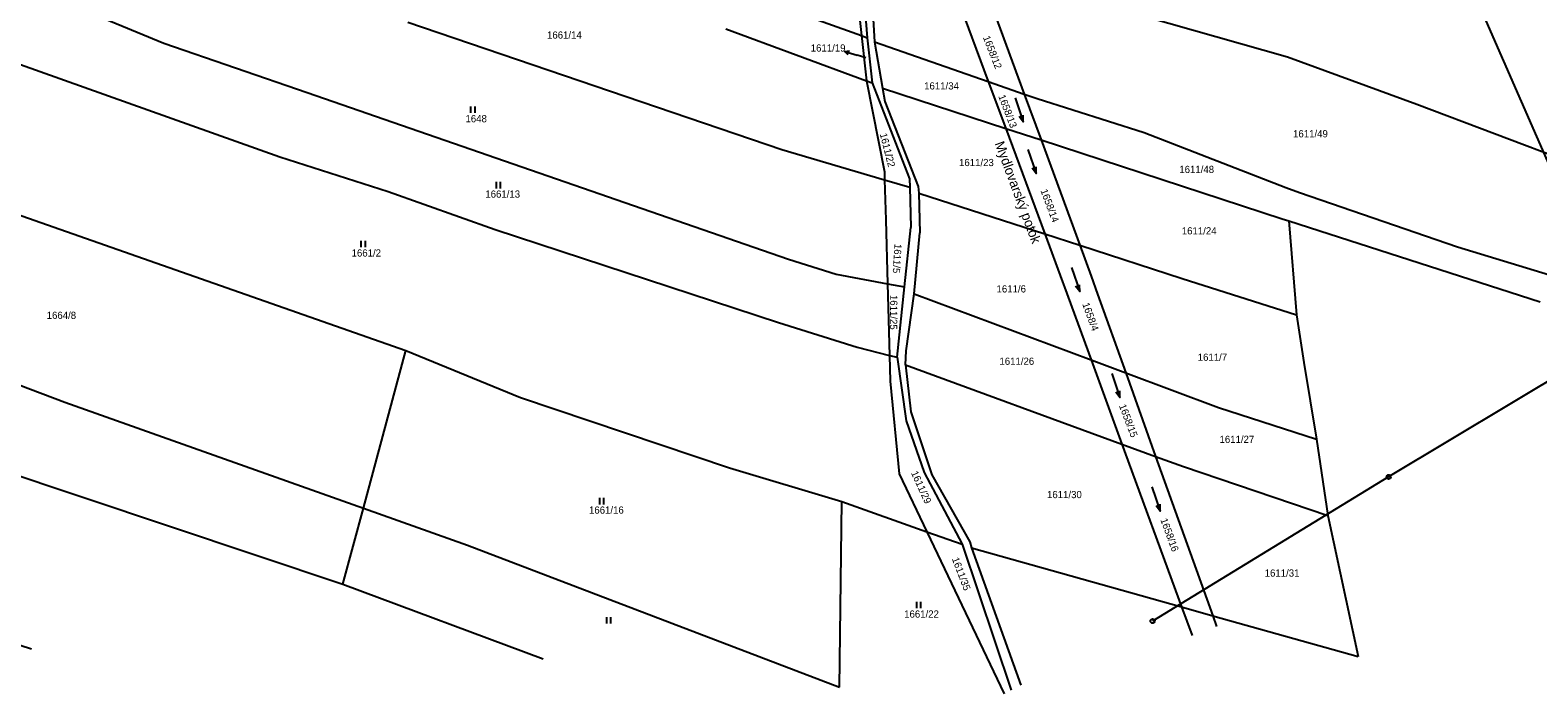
# Model space of a CAD drawing. Extents: x -763205 to -760228, y -1155311 to -1152844.
# Drawn here: x -761366.2 to -761010, y -1155167.3 to -1155010.6 of the extents above; entities that cross this region are included whole.
import ezdxf

# ---------------------------------------------------------------- set-up
doc = ezdxf.new("R2010")
doc.units = 0
for name, color, linetype in [('Vrstva 1', 7, 'Continuous'), ('Vrstva 12', 7, 'Continuous'), ('Vrstva 15', 7, 'Continuous'), ('Vrstva 16', 7, 'Continuous'), ('Vrstva 18', 7, 'Continuous'), ('Vrstva 25', 7, 'Continuous'), ('Vrstva 26', 7, 'Continuous'), ('Vrstva 6', 7, 'Continuous')]:
    doc.layers.add(name, color=color, linetype=linetype)

msp = doc.modelspace()

# ---------------------------------------------------------------- linework, layer by layer
at = {"layer": 'Vrstva 1'}
for p, q in [((-761172.54, -1154986.65), (-761169.79, -1155011.88)), ((-761151.21, -1154991.93), (-761139.81, -1155022.71)), ((-761142.75, -1154994.66), (-761131.35, -1155025.67)), ((-761169.79, -1155011.88), (-761168.71, -1155021.84)), ((-761168.71, -1155021.84), (-761168.58, -1155022.51)), ((-761168.58, -1155022.51), (-761164.37, -1155044.02)), ((-761139.81, -1155022.71), (-761135.71, -1155033.79)), ((-761131.35, -1155025.67), (-761127.36, -1155036.51)), ((-761135.71, -1155033.79), (-761126.49, -1155058.69)), ((-761417.92, -1155036.97), (-761277.43, -1155086.2)), ((-761127.36, -1155036.51), (-761118.22, -1155061.38)), ((-761164.37, -1155044.02), (-761164.32, -1155045.89)), ((-761164.32, -1155045.89), (-761164.05, -1155055.4)), ((-761164.05, -1155055.4), (-761163.62, -1155070.47)), ((-761126.49, -1155058.69), (-761122.29, -1155070.04)), ((-761118.22, -1155061.38), (-761115.54, -1155068.66)), ((-761163.62, -1155070.47), (-761163.14, -1155087.37)), ((-761122.29, -1155070.04), (-761121.84, -1155071.26)), ((-761121.84, -1155071.26), (-761115.54, -1155088.43)), ((-761115.54, -1155068.66), (-761114.02, -1155072.89)), ((-761114.02, -1155072.89), (-761107.35, -1155091.49)), ((-761287.49, -1155123.44), (-761277.43, -1155086.2)), ((-761163.14, -1155087.37), (-761162.97, -1155093.45)), ((-761115.54, -1155088.43), (-761108.25, -1155108.3)), ((-761107.35, -1155091.49), (-761100.28, -1155111.21)), ((-761162.97, -1155093.45), (-761160.85, -1155115.32)), ((-761108.25, -1155108.3), (-761094.13, -1155146.77)), ((-761376.78, -1155113.13), (-761292.34, -1155141.39)), ((-761100.28, -1155111.21), (-761086.78, -1155148.83)), ((-761160.85, -1155115.32), (-761154.31, -1155129.02)), ((-761292.34, -1155141.39), (-761287.49, -1155123.44)), ((-761154.31, -1155129.02), (-761136.03, -1155167.28)), ((-761094.13, -1155146.77), (-761091.64, -1155153.54)), ((-761086.78, -1155148.83), (-761085.86, -1155151.41))]:
    msp.add_line(p, q, dxfattribs=at)
at = {"layer": 'Vrstva 12'}
for p, q in [((-760989.63, -1155082.73), (-761022.16, -1155008.41)), ((-760989.63, -1155082.73), (-761045.22, -1155116.06)), ((-761045.22, -1155116.06), (-761100.99, -1155150.1))]:
    msp.add_line(p, q, dxfattribs=at)
at = {"layer": 'Vrstva 16'}
for p in [(-761173.7, -1155015.645), (-761168.75, -1155017.15)]:
    msp.add_line(p, (-761170.83, -1155016.52), dxfattribs=at)
msp.add_lwpolyline([(-761172.889, -1155016.415), (-761173.7, -1155015.645), (-761172.597, -1155015.459)], dxfattribs=at)
at = {"layer": 'Vrstva 25'}
for p, q in [((-761262.1, -1155030.13), (-761262.1, -1155028.63)), ((-761261.1, -1155030.13), (-761261.1, -1155028.63)), ((-761256.06, -1155047.93), (-761256.06, -1155046.43)), ((-761255.06, -1155047.93), (-761255.06, -1155046.43)), ((-761287.97, -1155061.84), (-761287.97, -1155060.34)), ((-761286.97, -1155061.84), (-761286.97, -1155060.34)), ((-761231.64, -1155122.54), (-761231.64, -1155121.04)), ((-761230.64, -1155122.54), (-761230.64, -1155121.04)), ((-761156.73, -1155147.09), (-761156.73, -1155145.59)), ((-761155.73, -1155147.09), (-761155.73, -1155145.59)), ((-761229.97, -1155150.71), (-761229.97, -1155149.21)), ((-761228.97, -1155150.71), (-761228.97, -1155149.21))]:
    msp.add_line(p, q, dxfattribs=at)
for points in [[(-761133.501, -1155026.551), (-761131.559, -1155032.229), (-761131.571, -1155030.647)], [(-761131.559, -1155032.229), (-761132.518, -1155030.971)], [(-761130.471, -1155038.781), (-761128.529, -1155044.459), (-761128.541, -1155042.877)], [(-761128.529, -1155044.459), (-761129.488, -1155043.201)], [(-761120.161, -1155066.581), (-761118.219, -1155072.259), (-761118.231, -1155070.677)], [(-761118.219, -1155072.259), (-761119.178, -1155071.001)], [(-761110.661, -1155091.651), (-761108.719, -1155097.329), (-761108.731, -1155095.747)], [(-761108.719, -1155097.329), (-761109.678, -1155096.071)], [(-761101.161, -1155118.441), (-761099.219, -1155124.119), (-761099.231, -1155122.537)], [(-761099.219, -1155124.119), (-761100.178, -1155122.861)]]:
    msp.add_lwpolyline(points, dxfattribs=at)
at = {"layer": 'Vrstva 26'}
for centre in [(-761045.22, -1155116.06), (-761100.99, -1155150.1)]:
    msp.add_circle(centre, 0.5, dxfattribs=at)
at = {"layer": 'Vrstva 6'}
for p, q in [((-761277.5, -1154973.14), (-761169.79, -1155011.88)), ((-761168.17, -1154988.95), (-761166.71, -1155013.3)), ((-761170.15, -1154990.02), (-761168.47, -1155012.36)), ((-761357.13, -1155004.33), (-761334.64, -1155013.67)), ((-761108.27, -1155005.79), (-761069.13, -1155016.91)), ((-761276.94, -1155008.72), (-761188.63, -1155038.79)), ((-761201.82, -1155010.26), (-761168.58, -1155022.51)), ((-761380.91, -1155014.27), (-761307.23, -1155040.5)), ((-761334.64, -1155013.67), (-761300.75, -1155025.32)), ((-761169.79, -1155011.88), (-761168.47, -1155012.36)), ((-761168.47, -1155012.36), (-761167.28, -1155022.99)), ((-761166.71, -1155013.3), (-761139.81, -1155022.71)), ((-761166.71, -1155013.3), (-761164.8, -1155024.29)), ((-761069.13, -1155016.91), (-761038.56, -1155028.06)), ((-761168.58, -1155022.51), (-761167.28, -1155022.99)), ((-761167.28, -1155022.99), (-761158.44, -1155045.68)), ((-761164.8, -1155024.29), (-761164.28, -1155027.45)), ((-761164.8, -1155024.29), (-761135.71, -1155033.79)), ((-761139.81, -1155022.71), (-761131.35, -1155025.67)), ((-761300.75, -1155025.32), (-761187.02, -1155064.68)), ((-761164.28, -1155027.45), (-761156.4, -1155047.53)), ((-761131.35, -1155025.67), (-761128.27, -1155026.75)), ((-761128.27, -1155026.75), (-761103.01, -1155034.72)), ((-761038.56, -1155028.06), (-760999.22, -1155042.88)), ((-761135.71, -1155033.79), (-761127.36, -1155036.51)), ((-761103.01, -1155034.72), (-761069.47, -1155047.71)), ((-761188.63, -1155038.79), (-761164.32, -1155045.89)), ((-761127.36, -1155036.51), (-761070.41, -1155055.1)), ((-761307.23, -1155040.5), (-761281.64, -1155048.64)), ((-761164.32, -1155045.89), (-761158.36, -1155047.63)), ((-761158.44, -1155045.68), (-761158.36, -1155047.63)), ((-761281.64, -1155048.64), (-761256.35, -1155057.67)), ((-761158.36, -1155047.63), (-761158.14, -1155057.21)), ((-761156.4, -1155047.53), (-761156.25, -1155049.03)), ((-761156.25, -1155049.03), (-761155.97, -1155058.42)), ((-761156.25, -1155049.03), (-761126.49, -1155058.69)), ((-761069.47, -1155047.71), (-761066.27, -1155048.93)), ((-761066.27, -1155048.93), (-761028.93, -1155061.73)), ((-761070.41, -1155055.1), (-761068.82, -1155055.61)), ((-761068.82, -1155055.61), (-761067, -1155077.76)), ((-761068.82, -1155055.61), (-761009.39, -1155074.74)), ((-761458.43, -1155060.54), (-761358.05, -1155098.4)), ((-761256.35, -1155057.67), (-761189.42, -1155079.64)), ((-761159.64, -1155071.21), (-761158.14, -1155057.21)), ((-761157.36, -1155072.81), (-761155.97, -1155058.42)), ((-761126.49, -1155058.69), (-761118.22, -1155061.38)), ((-761118.22, -1155061.38), (-761094.02, -1155069.24)), ((-761028.93, -1155061.73), (-761007.24, -1155068.34)), ((-761187.02, -1155064.68), (-761175.74, -1155068.21)), ((-761175.74, -1155068.21), (-761163.62, -1155070.47)), ((-761163.62, -1155070.47), (-761159.64, -1155071.21)), ((-761161.35, -1155087.82), (-761159.64, -1155071.21)), ((-761094.02, -1155069.24), (-761067, -1155077.76)), ((-761159.24, -1155086.32), (-761157.36, -1155072.81)), ((-761157.36, -1155072.81), (-761115.54, -1155088.43)), ((-761067, -1155077.76), (-761065.29, -1155089.06)), ((-761189.42, -1155079.64), (-761170.8, -1155085.43)), ((-761170.8, -1155085.43), (-761163.14, -1155087.37)), ((-761277.43, -1155086.2), (-761250.37, -1155097.33)), ((-761163.14, -1155087.37), (-761161.35, -1155087.82)), ((-761161.35, -1155087.82), (-761159.25, -1155102.83)), ((-761159.35, -1155089.62), (-761159.24, -1155086.32)), ((-761115.54, -1155088.43), (-761107.35, -1155091.49)), ((-761065.29, -1155089.06), (-761062.29, -1155107.15)), ((-761159.35, -1155089.62), (-761158.13, -1155100.7)), ((-761159.35, -1155089.62), (-761108.25, -1155108.3)), ((-761107.35, -1155091.49), (-761085.4, -1155099.69)), ((-761358.05, -1155098.4), (-761287.49, -1155123.44)), ((-761250.37, -1155097.33), (-761200.99, -1155113.9)), ((-761085.4, -1155099.69), (-761062.29, -1155107.15)), ((-761159.25, -1155102.83), (-761154.99, -1155115.02)), ((-761158.13, -1155100.7), (-761153.12, -1155115.6)), ((-761108.25, -1155108.3), (-761100.28, -1155111.21)), ((-761062.29, -1155107.15), (-761059.59, -1155125.14)), ((-761200.99, -1155113.9), (-761174.45, -1155121.89)), ((-761100.28, -1155111.21), (-761093.71, -1155113.61)), ((-761093.71, -1155113.61), (-761059.59, -1155125.14)), ((-761154.99, -1155115.02), (-761146, -1155131.96)), ((-761153.12, -1155115.6), (-761144.21, -1155131.39)), ((-761287.49, -1155123.44), (-761262.87, -1155132.18)), ((-761174.94, -1155165.67), (-761174.45, -1155121.89)), ((-761174.45, -1155121.89), (-761154.31, -1155129.02)), ((-761059.59, -1155125.14), (-761052.4, -1155158.5)), ((-761154.31, -1155129.02), (-761146, -1155131.96)), ((-761144.21, -1155131.39), (-761143.76, -1155132.82)), ((-761262.87, -1155132.18), (-761174.94, -1155165.67)), ((-761146, -1155131.96), (-761134.38, -1155166.4)), ((-761143.76, -1155132.82), (-761132.16, -1155165.22)), ((-761143.76, -1155132.82), (-761094.13, -1155146.77)), ((-761292.34, -1155141.39), (-761245.01, -1155159)), ((-761390.25, -1155148.78), (-761365.93, -1155156.67)), ((-761094.13, -1155146.77), (-761086.78, -1155148.83)), ((-761086.78, -1155148.83), (-761052.4, -1155158.5))]:
    msp.add_line(p, q, dxfattribs=at)

# ---------------------------------------------------------------- texts
at = {"layer": 'Vrstva 15'}
msp.add_text('Mydlovarský potok', height=2.3, rotation=290.43231, dxfattribs=at).set_placement((-761138.331, -1155037.333))
at = {"layer": 'Vrstva 16'}
msp.add_text('1611/19', height=1.7, dxfattribs=at).set_placement((-761181.777, -1155015.64))
at = {"layer": 'Vrstva 18'}
for s, height, p in [('1661/14', 1.7, (-761244.087, -1155012.58)), ('1611/19', 0.1, (-761168.727, -1155017.15)), ('1611/34', 1.7, (-761154.977, -1155024.59)), ('1648', 1.7, (-761263.357, -1155032.33)), ('1611/49', 1.7, (-761067.797, -1155035.89)), ('1611/23', 1.7, (-761146.727, -1155042.68)), ('1611/48', 1.7, (-761094.677, -1155044.31)), ('1661/13', 1.7, (-761258.667, -1155050.13)), ('1611/24', 1.7, (-761094.087, -1155058.81)), ('1661/2', 1.7, (-761290.267, -1155064.04)), ('1611/6', 1.7, (-761137.867, -1155072.52)), ('1664/8', 1.7, (-761362.317, -1155078.76)), ('1611/26', 1.7, (-761137.187, -1155089.6)), ('1611/7', 1.7, (-761090.327, -1155088.65)), ('1611/27', 1.7, (-761085.177, -1155108.04)), ('1611/30', 1.7, (-761125.937, -1155121.08)), ('1661/16', 1.7, (-761234.167, -1155124.74)), ('1611/31', 1.7, (-761074.507, -1155139.61)), ('1661/22', 1.7, (-761159.697, -1155149.29))]:
    msp.add_text(s, height=height, dxfattribs=at).set_placement(p)
for s, rotation, p in [('1658/12', 291.34904, (-761141.107, -1155012.286)), ('1658/13', 290.94797, (-761137.49, -1155026.177)), ('1611/22', 284.30166, (-761165.463, -1155035.111)), ('1658/14', 290.43231, (-761127.513, -1155048.458)), ('1611/5', 266.42538, (-761161.964, -1155061.002)), ('1611/25', 269.46205, (-761162.974, -1155073.083)), ('1658/4', 290.03124, (-761117.635, -1155075.259)), ('1658/15', 290.89067, (-761108.97, -1155099.247)), ('1611/29', 294.38571, (-761158.118, -1155115.108)), ('1658/16', 290.14583, (-761099.185, -1155126.179)), ('1611/35', 290.89067, (-761148.45, -1155135.407))]:
    msp.add_text(s, height=1.7, rotation=rotation, dxfattribs=at).set_placement(p)

doc.saveas('drawing.dxf')
